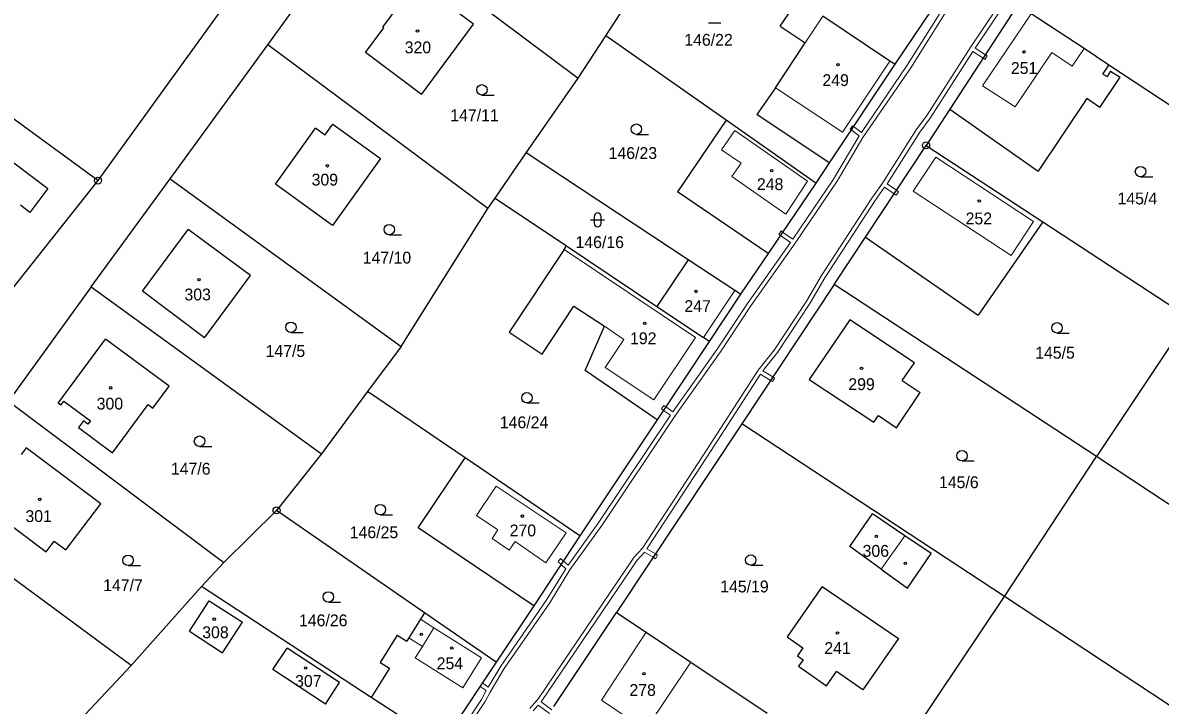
# Model space of a CAD drawing. Extents: x -694609 to -690140, y -1033292 to -1029794.
# Drawn here: x -692949.2 to -692786, y -1031625.4 to -1031527.4 of the extents above; entities that cross this region are included whole.
import ezdxf
from ezdxf.enums import TextEntityAlignment as Align

# ---------------------------------------------------------------- set-up
doc = ezdxf.new("R2010")
doc.units = 0
doc.header["$LTSCALE"] = 0.68
for name, color, linetype, lineweight in [('1', 7, 'Continuous', 25), ('13', 7, 'Continuous', 13), ('3', 7, 'Continuous', 25), ('4', 7, 'Continuous', 13), ('5', 7, 'Continuous', 25), ('8', 7, 'Continuous', 25)]:
    doc.layers.add(name, color=color, linetype=linetype, lineweight=lineweight)
doc.layers.add('2', color=7, linetype='Continuous')

msp = doc.modelspace()

# ---------------------------------------------------------------- linework, layer by layer
at = {"layer": '1'}
for p, q in [((-692908.5, -1031508.61), (-692938.37, -1031550.06)), ((-692914.01, -1031530.6), (-692900.63, -1031512.05)), ((-692900.63, -1031512.05), (-692869.49, -1031535.38)), ((-692865.52, -1031529.27), (-692856.64, -1031515.64)), ((-692813.63, -1031517.87), (-692824.08, -1031533.37)), ((-692897.5, -1031528.03), (-692894.26, -1031523.64)), ((-692884.48, -1031527.6), (-692889.11, -1031524.19)), ((-692840.5, -1031527.92), (-692837.93, -1031524.09)), ((-692796.91, -1031531.13), (-692804.51, -1031526.12)), ((-692891.95, -1031537.7), (-692884.48, -1031527.6)), ((-692824.77, -1031532.91), (-692834.4, -1031526.46)), ((-692900, -1031531.68), (-692897.37, -1031528.15)), ((-692897.5, -1031528.03), (-692897.37, -1031528.15)), ((-692869.49, -1031535.38), (-692865.52, -1031529.27)), ((-692848.25, -1031541.4), (-692865.52, -1031529.27)), ((-692840.5, -1031527.92), (-692836.94, -1031530.31)), ((-692928.02, -1031549.83), (-692914.01, -1031530.6)), ((-692882.45, -1031554.08), (-692914.01, -1031530.6)), ((-692841.19, -1031536.76), (-692836.94, -1031530.31)), ((-692793.35, -1031533.48), (-692796.91, -1031531.13)), ((-692891.95, -1031537.7), (-692900, -1031531.68)), ((-692824.08, -1031533.37), (-692833.46, -1031547.5)), ((-692824.08, -1031533.37), (-692824.77, -1031532.91)), ((-692794.21, -1031534.77), (-692793.35, -1031533.48)), ((-692793.12, -1031534.38), (-692793.62, -1031535.14)), ((-692768.7, -1031549.76), (-692793.35, -1031533.48)), ((-692793.12, -1031534.38), (-692791.76, -1031535.24)), ((-692876.92, -1031546.1), (-692869.49, -1031535.38)), ((-692794.63, -1031539.55), (-692791.76, -1031535.24)), ((-692794.21, -1031534.77), (-692793.62, -1031535.14)), ((-692841.19, -1031536.76), (-692843.84, -1031540.57)), ((-692796.54, -1031538.27), (-692803.49, -1031548.7)), ((-692794.63, -1031539.55), (-692796.54, -1031538.27)), ((-692938.37, -1031550.06), (-692952.88, -1031539.48)), ((-692833.46, -1031547.5), (-692843.84, -1031540.57)), ((-692816.15, -1031539.83), (-692819.57, -1031545.01)), ((-692816.15, -1031539.83), (-692803.49, -1031548.7)), ((-692912.91, -1031550.58), (-692907.16, -1031542.56)), ((-692905.83, -1031543.55), (-692907.16, -1031542.56)), ((-692905.83, -1031543.55), (-692904.69, -1031541.96)), ((-692904.69, -1031541.96), (-692897.84, -1031546.89)), ((-692848.25, -1031541.4), (-692855.23, -1031551.69)), ((-692835.39, -1031550.42), (-692848.25, -1031541.4)), ((-692953.28, -1031545.38), (-692945.56, -1031551.2)), ((-692828.27, -1031558.18), (-692819.57, -1031545.01)), ((-692819.57, -1031545.01), (-692802.84, -1031555.98)), ((-692897.84, -1031546.89), (-692904.74, -1031556.49)), ((-692881.4, -1031552.56), (-692876.92, -1031546.1)), ((-692853.7, -1031561.43), (-692876.92, -1031546.1)), ((-692833.46, -1031547.5), (-692835.39, -1031550.42)), ((-692938.37, -1031550.06), (-692971.22, -1031591.47)), ((-692939.33, -1031565.31), (-692928.02, -1031549.83)), ((-692928.02, -1031549.83), (-692894.88, -1031573.85)), ((-692904.74, -1031556.49), (-692912.91, -1031550.58)), ((-692835.39, -1031550.42), (-692842.22, -1031560.51)), ((-692945.56, -1031551.2), (-692948.12, -1031554.62)), ((-692842.22, -1031560.51), (-692855.23, -1031551.69)), ((-692948.12, -1031554.62), (-692949.47, -1031553.61)), ((-692882.45, -1031554.08), (-692881.4, -1031552.56)), ((-692881.4, -1031552.56), (-692871.15, -1031559.43)), ((-692894.88, -1031573.85), (-692882.45, -1031554.08)), ((-692931.97, -1031565.95), (-692925.4, -1031557.08)), ((-692802.84, -1031555.98), (-692812.09, -1031569.36)), ((-692802.84, -1031555.98), (-692781.88, -1031569.73)), ((-692832.77, -1031564.98), (-692828.27, -1031558.18)), ((-692828.27, -1031558.18), (-692812.09, -1031569.36)), ((-692871.48, -1031559.95), (-692879.38, -1031571.82)), ((-692871.48, -1031559.95), (-692871.15, -1031559.43)), ((-692871.15, -1031559.43), (-692858.18, -1031568.11)), ((-692842.22, -1031560.51), (-692846.2, -1031566.38)), ((-692853.7, -1031561.43), (-692858.18, -1031568.11)), ((-692847.02, -1031565.84), (-692853.7, -1031561.43)), ((-692939.33, -1031565.31), (-692951.21, -1031581.69)), ((-692939.33, -1031565.31), (-692906.29, -1031589.25)), ((-692832.77, -1031564.98), (-692846, -1031584.95)), ((-692795.11, -1031589.67), (-692832.77, -1031564.98)), ((-692923.08, -1031572.61), (-692931.97, -1031565.95)), ((-692846.2, -1031566.38), (-692850.67, -1031573.15)), ((-692846.2, -1031566.38), (-692847.02, -1031565.84)), ((-692874.66, -1031574.96), (-692870.08, -1031568.08)), ((-692870.08, -1031568.08), (-692865.69, -1031570.96)), ((-692858.18, -1031568.11), (-692851.52, -1031572.57)), ((-692830.52, -1031570.04), (-692836.37, -1031578.62)), ((-692821.26, -1031576.2), (-692830.52, -1031570.04)), ((-692781.88, -1031569.73), (-692795.11, -1031589.67)), ((-692879.38, -1031571.82), (-692874.66, -1031574.96)), ((-692868.47, -1031577.31), (-692865.69, -1031570.96)), ((-692944.08, -1031582), (-692937.27, -1031572.82)), ((-692928.17, -1031579.57), (-692937.27, -1031572.82)), ((-692850.67, -1031573.15), (-692858.15, -1031584.41)), ((-692850.67, -1031573.15), (-692851.52, -1031572.57)), ((-692894.88, -1031573.85), (-692899.68, -1031580.33)), ((-692823, -1031578.76), (-692821.26, -1031576.2)), ((-692858.15, -1031584.41), (-692868.47, -1031577.31)), ((-692930.5, -1031582.71), (-692928.17, -1031579.57)), ((-692836.37, -1031578.62), (-692827.07, -1031584.73)), ((-692823, -1031578.76), (-692820.43, -1031580.48)), ((-692951.21, -1031581.69), (-692920.32, -1031604.87)), ((-692943.67, -1031582.3), (-692943.25, -1031581.73)), ((-692943.25, -1031581.73), (-692939.45, -1031584.54)), ((-692899.68, -1031580.33), (-692906.29, -1031589.25)), ((-692885.7, -1031589.84), (-692899.68, -1031580.33)), ((-692823.8, -1031585.53), (-692820.43, -1031580.48)), ((-692943.67, -1031582.3), (-692944.08, -1031582)), ((-692936.3, -1031589.11), (-692931.18, -1031582.2)), ((-692931.18, -1031582.2), (-692930.5, -1031582.71)), ((-692940.45, -1031584.55), (-692941.16, -1031585.51)), ((-692858.15, -1031584.41), (-692869.24, -1031601.04)), ((-692846, -1031584.95), (-692864, -1031612.03)), ((-692808.34, -1031609.74), (-692846, -1031584.95)), ((-692827.07, -1031584.73), (-692826.42, -1031583.78)), ((-692826.42, -1031583.78), (-692823.8, -1031585.53)), ((-692941.16, -1031585.51), (-692936.3, -1031589.11)), ((-692948.67, -1031588.42), (-692949.38, -1031589.37)), ((-692937.94, -1031596.44), (-692948.67, -1031588.42)), ((-692906.29, -1031589.25), (-692912.75, -1031597.39)), ((-692892.43, -1031599.9), (-692885.7, -1031589.84)), ((-692869.24, -1031601.04), (-692885.7, -1031589.84)), ((-692808.34, -1031609.74), (-692795.11, -1031589.67)), ((-692723.58, -1031636.99), (-692795.11, -1031589.67)), ((-692942.98, -1031603.05), (-692937.94, -1031596.44)), ((-692933.59, -1031619.64), (-692962.9, -1031598.03)), ((-692954.78, -1031596.58), (-692945.81, -1031603.31)), ((-692912.75, -1031597.39), (-692920.32, -1031604.87)), ((-692891.53, -1031612.07), (-692912.75, -1031597.39)), ((-692830.52, -1031602.56), (-692827.26, -1031597.89)), ((-692822.61, -1031601.03), (-692827.26, -1031597.89)), ((-692875.84, -1031611.06), (-692892.43, -1031599.9)), ((-692869.24, -1031601.04), (-692875.84, -1031611.06)), ((-692818.83, -1031603.58), (-692822.61, -1031601.03)), ((-692945.81, -1031603.31), (-692944.62, -1031601.78)), ((-692944.62, -1031601.78), (-692942.98, -1031603.05)), ((-692826.04, -1031605.82), (-692830.52, -1031602.56)), ((-692822.22, -1031608.56), (-692818.83, -1031603.58)), ((-692826.04, -1031605.82), (-692822.22, -1031608.56)), ((-692933.59, -1031619.64), (-692923.51, -1031608.29)), ((-692834.48, -1031608.3), (-692839.51, -1031615.51)), ((-692834.48, -1031608.3), (-692823.55, -1031615.76)), ((-692925.25, -1031614.73), (-692922.39, -1031610.36)), ((-692922.39, -1031610.36), (-692917.65, -1031613.45)), ((-692875.84, -1031611.06), (-692881.24, -1031619.19)), ((-692826.6, -1031637.03), (-692808.34, -1031609.74)), ((-692736.91, -1031656.87), (-692808.34, -1031609.74)), ((-692891.53, -1031612.07), (-692892.12, -1031613.01)), ((-692881.24, -1031619.19), (-692891.53, -1031612.07)), ((-692872.96, -1031625.53), (-692864, -1031612.03)), ((-692864, -1031612.03), (-692859.74, -1031614.88)), ((-692920.51, -1031617.83), (-692917.65, -1031613.45)), ((-692892.12, -1031613.01), (-692893.78, -1031615.66)), ((-692925.25, -1031614.73), (-692920.51, -1031617.83)), ((-692895.44, -1031615.29), (-692897.89, -1031619.2)), ((-692895.44, -1031615.29), (-692894.08, -1031616.14)), ((-692893.78, -1031615.66), (-692894.08, -1031616.14)), ((-692859.74, -1031614.88), (-692853.3, -1031619.19)), ((-692839.51, -1031615.51), (-692837.24, -1031617.1)), ((-692823.55, -1031615.76), (-692828.64, -1031623.13)), ((-692913.26, -1031620.24), (-692911.24, -1031617.14)), ((-692903.7, -1031622.07), (-692911.24, -1031617.14)), ((-692837.24, -1031617.1), (-692838.03, -1031618.24)), ((-692897.89, -1031619.2), (-692896.53, -1031620.05)), ((-692881.24, -1031619.19), (-692888.99, -1031630.78)), ((-692853.3, -1031619.19), (-692842.36, -1031626.5)), ((-692838.03, -1031618.24), (-692837.21, -1031618.81)), ((-692837.21, -1031618.81), (-692837.87, -1031619.75)), ((-692942.66, -1031629.3), (-692933.59, -1031619.64)), ((-692905.72, -1031625.17), (-692913.26, -1031620.24)), ((-692896.53, -1031620.05), (-692899.15, -1031624.23)), ((-692837.87, -1031619.75), (-692833.85, -1031622.55)), ((-692833.85, -1031622.55), (-692832.42, -1031620.5)), ((-692828.64, -1031623.13), (-692832.42, -1031620.5)), ((-692905.72, -1031625.17), (-692903.7, -1031622.07)), ((-692888.99, -1031630.78), (-692899.15, -1031624.23))]:
    msp.add_line(p, q, dxfattribs=at)
for points in [[(-692804.51, -1031526.12), (-692806.41, -1031524.86), (-692816.15, -1031539.83)], [(-692923.08, -1031572.61), (-692916.48, -1031563.68), (-692925.4, -1031557.08)], [(-692939.45, -1031584.54), (-692939.8, -1031585.02), (-692940.45, -1031584.55)], [(-692899.15, -1031624.23), (-692923.51, -1031608.29), (-692920.32, -1031604.87)]]:
    msp.add_lwpolyline(points, dxfattribs=at)
at = {"layer": '13'}
for points in [[(-692793.95, -1031502.2), (-692813.14, -1031530.87), (-692819.48, -1031540.74), (-692820.99, -1031542.78), (-692825.84, -1031550.45), (-692827.37, -1031552.57), (-692834.57, -1031563.66), (-692836.73, -1031567.37), (-692841.38, -1031574.4), (-692843.66, -1031577.25), (-692851.49, -1031589.41), (-692860.25, -1031602.81), (-692861.5, -1031604.15), (-692875.16, -1031624.38), (-692876.43, -1031625.81)], [(-692873.27, -1031626), (-692874.77, -1031624.88), (-692861.02, -1031604.52), (-692859.97, -1031603.38), (-692858.74, -1031604.12), (-692858.41, -1031603.62), (-692859.61, -1031602.9), (-692851.01, -1031589.76), (-692843.34, -1031577.85), (-692841.89, -1031578.74), (-692841.56, -1031578.24), (-692842.98, -1031577.36), (-692840.89, -1031574.74), (-692836.23, -1031567.7), (-692834.08, -1031564), (-692826.86, -1031552.9), (-692825.52, -1031551.02), (-692824.16, -1031551.96), (-692823.83, -1031551.45), (-692825.18, -1031550.52), (-692820.49, -1031543.1), (-692818.99, -1031541.08), (-692812.87, -1031531.56), (-692811.39, -1031532.51), (-692811.06, -1031532.01), (-692812.54, -1031531.06), (-692793.72, -1031502.94)], [(-692896.56, -1031645.33), (-692882.82, -1031624.83), (-692882.12, -1031623.46), (-692880.08, -1031620.07), (-692873.55, -1031610.64), (-692870.66, -1031605.91), (-692866.07, -1031599.54), (-692855.61, -1031583.86), (-692849.06, -1031574.62), (-692844.71, -1031568.04), (-692838.37, -1031559.05), (-692832.33, -1031550.15), (-692828.63, -1031543.9), (-692821.78, -1031533.86), (-692814.94, -1031522.92)], [(-692815.54, -1031522.77), (-692822.27, -1031533.51), (-692828.85, -1031543.15), (-692830, -1031542.28), (-692830.33, -1031542.78), (-692829.17, -1031543.66), (-692832.85, -1031549.84), (-692838.69, -1031558.45), (-692840.15, -1031557.45), (-692840.48, -1031557.94), (-692839.03, -1031558.94), (-692845.19, -1031567.68), (-692849.52, -1031574.23), (-692855.92, -1031583.25), (-692856.91, -1031582.54), (-692857.24, -1031583.04), (-692856.26, -1031583.74), (-692866.59, -1031599.23), (-692870.92, -1031605.25), (-692871.61, -1031604.64), (-692871.94, -1031605.14), (-692871.26, -1031605.75), (-692874.05, -1031610.31), (-692880.58, -1031619.73), (-692882.38, -1031622.73), (-692883.22, -1031622.15), (-692883.55, -1031622.65), (-692882.68, -1031623.24)], [(-692882.68, -1031623.24), (-692883.34, -1031624.53), (-692896.9, -1031644.75)], [(-692875.95, -1031626.17), (-692875.2, -1031625.32), (-692873.61, -1031626.51)]]:
    msp.add_lwpolyline(points, dxfattribs=at)
for points in [[(-692811.06, -1031532.01), (-692811.39, -1031532.51), (-692811.13, -1031532.68), (-692810.82, -1031532.17)], [(-692830.33, -1031542.78), (-692830, -1031542.28), (-692830.12, -1031542.19), (-692830.48, -1031542.67)], [(-692823.83, -1031551.45), (-692824.16, -1031551.96), (-692823.86, -1031552.17), (-692823.53, -1031551.66)], [(-692840.48, -1031557.94), (-692840.15, -1031557.45), (-692840.37, -1031557.29), (-692840.71, -1031557.79)], [(-692841.56, -1031578.24), (-692841.89, -1031578.74), (-692841.61, -1031578.91), (-692841.3, -1031578.4)], [(-692857.2, -1031582.33), (-692857.55, -1031582.82), (-692857.24, -1031583.04), (-692856.91, -1031582.54)], [(-692871.94, -1031605.14), (-692871.61, -1031604.64), (-692872.01, -1031604.29), (-692872.34, -1031604.79)], [(-692858.41, -1031603.62), (-692858.74, -1031604.12), (-692858.39, -1031604.33), (-692858.09, -1031603.81)]]:
    msp.add_lwpolyline(points, close=True, dxfattribs=at)
at = {"layer": '3'}
for p, q in [((-692850.773, -1031527.41), (-692849.023, -1031527.41)), ((-692883.283, -1031537.79), (-692881.533, -1031537.79)), ((-692861.133, -1031543.43), (-692859.383, -1031543.43)), ((-692788.813, -1031549.52), (-692787.063, -1031549.52)), ((-692867.201, -1031555.211), (-692867.201, -1031556.212)), ((-692866.199, -1031556.212), (-692866.199, -1031555.211)), ((-692867.701, -1031555.711), (-692865.699, -1031555.711)), ((-692896.573, -1031557.84), (-692894.823, -1031557.84)), ((-692910.683, -1031571.86), (-692908.933, -1031571.86)), ((-692800.793, -1031571.94), (-692799.043, -1031571.94)), ((-692876.833, -1031581.97), (-692875.083, -1031581.97)), ((-692923.793, -1031588.21), (-692922.043, -1031588.21)), ((-692814.423, -1031590.29), (-692812.673, -1031590.29)), ((-692897.863, -1031598.03), (-692896.113, -1031598.03)), ((-692934.033, -1031605.3), (-692932.283, -1031605.3)), ((-692844.723, -1031605.26), (-692842.973, -1031605.26)), ((-692905.313, -1031610.56), (-692903.563, -1031610.56))]:
    msp.add_line(p, q, dxfattribs=at)
for centre in [(-692883.2829, -1031537.0398), (-692861.1329, -1031542.6798), (-692788.8129, -1031548.7698), (-692896.5729, -1031557.0898), (-692910.6829, -1031571.1098), (-692800.7929, -1031571.1898), (-692876.8329, -1031581.2198), (-692923.7929, -1031587.4598), (-692814.4229, -1031589.5398), (-692897.8629, -1031597.2798), (-692934.0329, -1031604.5498), (-692844.7229, -1031604.5098), (-692905.3129, -1031609.8098)]:
    msp.add_circle(centre, 0.75, dxfattribs=at)
for centre, start, end in [((-692866.7, -1031555.2109), 0, 180), ((-692866.7, -1031556.2109), 180, 359.98789)]:
    msp.add_arc(centre, 0.5, start, end, dxfattribs=at)
at = {"layer": '4'}
for p, q in [((-692804.51, -1031526.12), (-692811.49, -1031536.48)), ((-692836.94, -1031530.31), (-692834.4, -1031526.46)), ((-692796.91, -1031531.13), (-692798.62, -1031533.66)), ((-692801.54, -1031531.69), (-692806.81, -1031539.47)), ((-692801.54, -1031531.69), (-692798.62, -1031533.66)), ((-692824.77, -1031532.91), (-692831.58, -1031543.1)), ((-692841.19, -1031536.76), (-692831.58, -1031543.1)), ((-692806.81, -1031539.47), (-692811.49, -1031536.48)), ((-692848.91, -1031545.63), (-692847.02, -1031542.89)), ((-692836.57, -1031550.12), (-692847.02, -1031542.89)), ((-692846.12, -1031547.56), (-692848.91, -1031545.63)), ((-692818.2, -1031546.7), (-692804.17, -1031555.91)), ((-692839.68, -1031554.86), (-692836.57, -1031550.12)), ((-692804.17, -1031555.91), (-692807.38, -1031560.8)), ((-692871.48, -1031559.95), (-692852.65, -1031572.6)), ((-692847.02, -1031565.84), (-692851.52, -1031572.57)), ((-692865.69, -1031570.96), (-692862.92, -1031572.85)), ((-692862.92, -1031572.85), (-692865.59, -1031576.86)), ((-692852.65, -1031572.6), (-692858.63, -1031581.5)), ((-692865.59, -1031576.86), (-692858.63, -1031581.5)), ((-692884.06, -1031598.14), (-692881.22, -1031593.9)), ((-692881.22, -1031593.9), (-692871.21, -1031600.6)), ((-692880.99, -1031600.2), (-692884.06, -1031598.14)), ((-692881.82, -1031601.44), (-692880.99, -1031600.2)), ((-692871.21, -1031600.6), (-692874.1, -1031604.92)), ((-692822.61, -1031601.03), (-692826.04, -1031605.82)), ((-692879.37, -1031603.08), (-692881.82, -1031601.44)), ((-692878.53, -1031601.84), (-692879.37, -1031603.08)), ((-692878.53, -1031601.84), (-692874.1, -1031604.92)), ((-692892.12, -1031613.01), (-692890.17, -1031614.25)), ((-692890.17, -1031614.25), (-692891.83, -1031616.9)), ((-692890.17, -1031614.25), (-692883.33, -1031618.54)), ((-692891.83, -1031616.9), (-692893.78, -1031615.66)), ((-692866.14, -1031624.63), (-692859.74, -1031614.88)), ((-692891.83, -1031616.9), (-692892.86, -1031618.54)), ((-692892.86, -1031618.54), (-692886.02, -1031622.83)), ((-692883.33, -1031618.54), (-692886.02, -1031622.83)), ((-692859.83, -1031628.89), (-692853.3, -1031619.19)), ((-692866.14, -1031624.63), (-692859.83, -1031628.89))]:
    msp.add_line(p, q, dxfattribs=at)
for points in [[(-692807.38, -1031560.8), (-692821.41, -1031551.59), (-692818.2, -1031546.7)], [(-692839.68, -1031554.86), (-692847.46, -1031549.49), (-692846.12, -1031547.56)]]:
    msp.add_lwpolyline(points, dxfattribs=at)
at = {"layer": '5'}
for centre in [(-692892.5268, -1031528.6092), (-692805.5268, -1031531.5892), (-692832.2168, -1031533.4192), (-692905.4568, -1031547.9392), (-692841.7268, -1031548.6292), (-692811.9568, -1031552.9992), (-692923.8668, -1031564.2792), (-692852.5768, -1031565.9692), (-692859.9268, -1031570.5292), (-692828.8368, -1031577.0092), (-692936.5468, -1031579.7992), (-692946.7068, -1031595.8192), (-692877.4768, -1031598.2192), (-692826.7068, -1031601.1192), (-692822.5368, -1031604.9692), (-692921.6868, -1031612.9992), (-692891.9868, -1031615.1592), (-692832.2868, -1031614.9892), (-692887.6068, -1031617.1192), (-692908.5568, -1031620.0092), (-692860.0568, -1031620.8092)]:
    msp.add_circle(centre, 0.175, dxfattribs=at)
at = {"layer": '8'}
for centre, radius in [((-692819.57, -1031545.0099), 0.5), ((-692819.57, -1031545.0099), 0.0303), ((-692938.37, -1031550.0599), 0.5), ((-692938.37, -1031550.0599), 0.0303), ((-692912.75, -1031597.3899), 0.5), ((-692912.75, -1031597.3899), 0.0303)]:
    msp.add_circle(centre, radius, dxfattribs=at)

# ---------------------------------------------------------------- texts
at = {"layer": '2'}
for s, p in [('146/22', (-692850.78, -1031530.715)), ('320', (-692892.469, -1031531.795)), ('251', (-692805.519, -1031534.755)), ('249', (-692832.549, -1031536.495)), ('147/11', (-692884.35, -1031541.535)), ('146/23', (-692861.64, -1031546.965)), ('309', (-692905.819, -1031550.775)), ('248', (-692841.949, -1031551.425)), ('145/4', (-692789.27, -1031553.475)), ('252', (-692812.009, -1031556.345)), ('146/16', (-692866.39, -1031559.745)), ('147/10', (-692896.91, -1031561.965)), ('303', (-692924.059, -1031567.255)), ('247', (-692852.349, -1031568.925)), ('192', (-692860.139, -1031573.535)), ('147/5', (-692911.48, -1031575.365)), ('145/5', (-692801.08, -1031575.615)), ('299', (-692828.829, -1031580.125)), ('300', (-692936.649, -1031582.915)), ('146/24', (-692877.24, -1031585.595)), ('147/6', (-692925.06, -1031592.255)), ('145/6', (-692814.88, -1031594.195)), ('301', (-692946.869, -1031599.055)), ('146/25', (-692898.77, -1031601.375)), ('270', (-692877.409, -1031601.115)), ('306', (-692826.789, -1031604.045)), ('147/7', (-692934.77, -1031608.975)), ('145/19', (-692845.63, -1031609.155)), ('146/26', (-692906.05, -1031614.015)), ('308', (-692921.509, -1031615.725)), ('241', (-692832.279, -1031617.995)), ('254', (-692887.879, -1031620.185)), ('307', (-692908.189, -1031622.715)), ('278', (-692860.229, -1031624.005))]:
    msp.add_text(s, height=1.7, dxfattribs=at).set_placement(p, align=Align.CENTER)

doc.saveas('drawing.dxf')
